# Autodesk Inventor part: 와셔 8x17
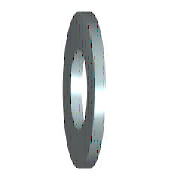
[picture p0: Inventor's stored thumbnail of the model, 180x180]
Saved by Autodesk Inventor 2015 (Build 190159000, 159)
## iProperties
IsCustomPart: 1
Created: 2012-02
Part Number: 와셔 8x17
Material: 강철, 연강
Description: 평면 와셔
Document SubType Name: Modeling
Standard: KS B 1326
Designer: mduedu
Standards Organization: KS
Language: ko-KR
Size Designation: 8x17
Categories: <MemberInstance><Categories><Category DisplayName="조임쇠" InternalName="e4da775c-781d-43d5-af7c-5136215cf5a6" Mnemonic="FSTN"><Category DisplayName="와셔" InternalN
Density: 1 g/cm^3
Appearance: 노란색
Author: mduedu
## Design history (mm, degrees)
sketch "스케치"
  geometry: C1 r 8.5 at (0, 0); C2 r 4.2 at (0, 0); 1 further point
  constraints: 2 centre point, 2 coincident
  dimensions: "d0" = 8.4 diameter of C2 (= SD1); "d1" = 17 diameter of C1 (= SD2)
extrude "본체" new body sketch "스케치" distance "d2" = 1.6 (= SD); taper "d3" = 0 deg
workaxis "Work Axis1"
workplane "Work Plane1"
body "Solid1"
other parameters: "SD1" = 8.4 [user parameter; used in 1 equation term], "SD2" = 17 [user parameter; used in 1 equation term], "SD" = 1.6 [user parameter; used in 1 equation term], "d4" = 0, "d5" = 0, "d6" = 0, "d7" = 0, "NND" = 8 [user parameter]
